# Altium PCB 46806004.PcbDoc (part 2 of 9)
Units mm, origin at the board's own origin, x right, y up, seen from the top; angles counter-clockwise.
Board outline 130 x 105 mm, 8 copper layers (Top Layer, P1-GND, L1-Signal, L2-Signal, L3-Signal, L4-Signal, P2-GND, Bottom Layer), stack 1.63 mm thick; 796 components, 496 nets, 2808 pads, 1195 vias.
Unrouted connection lines stored in the file: 1.
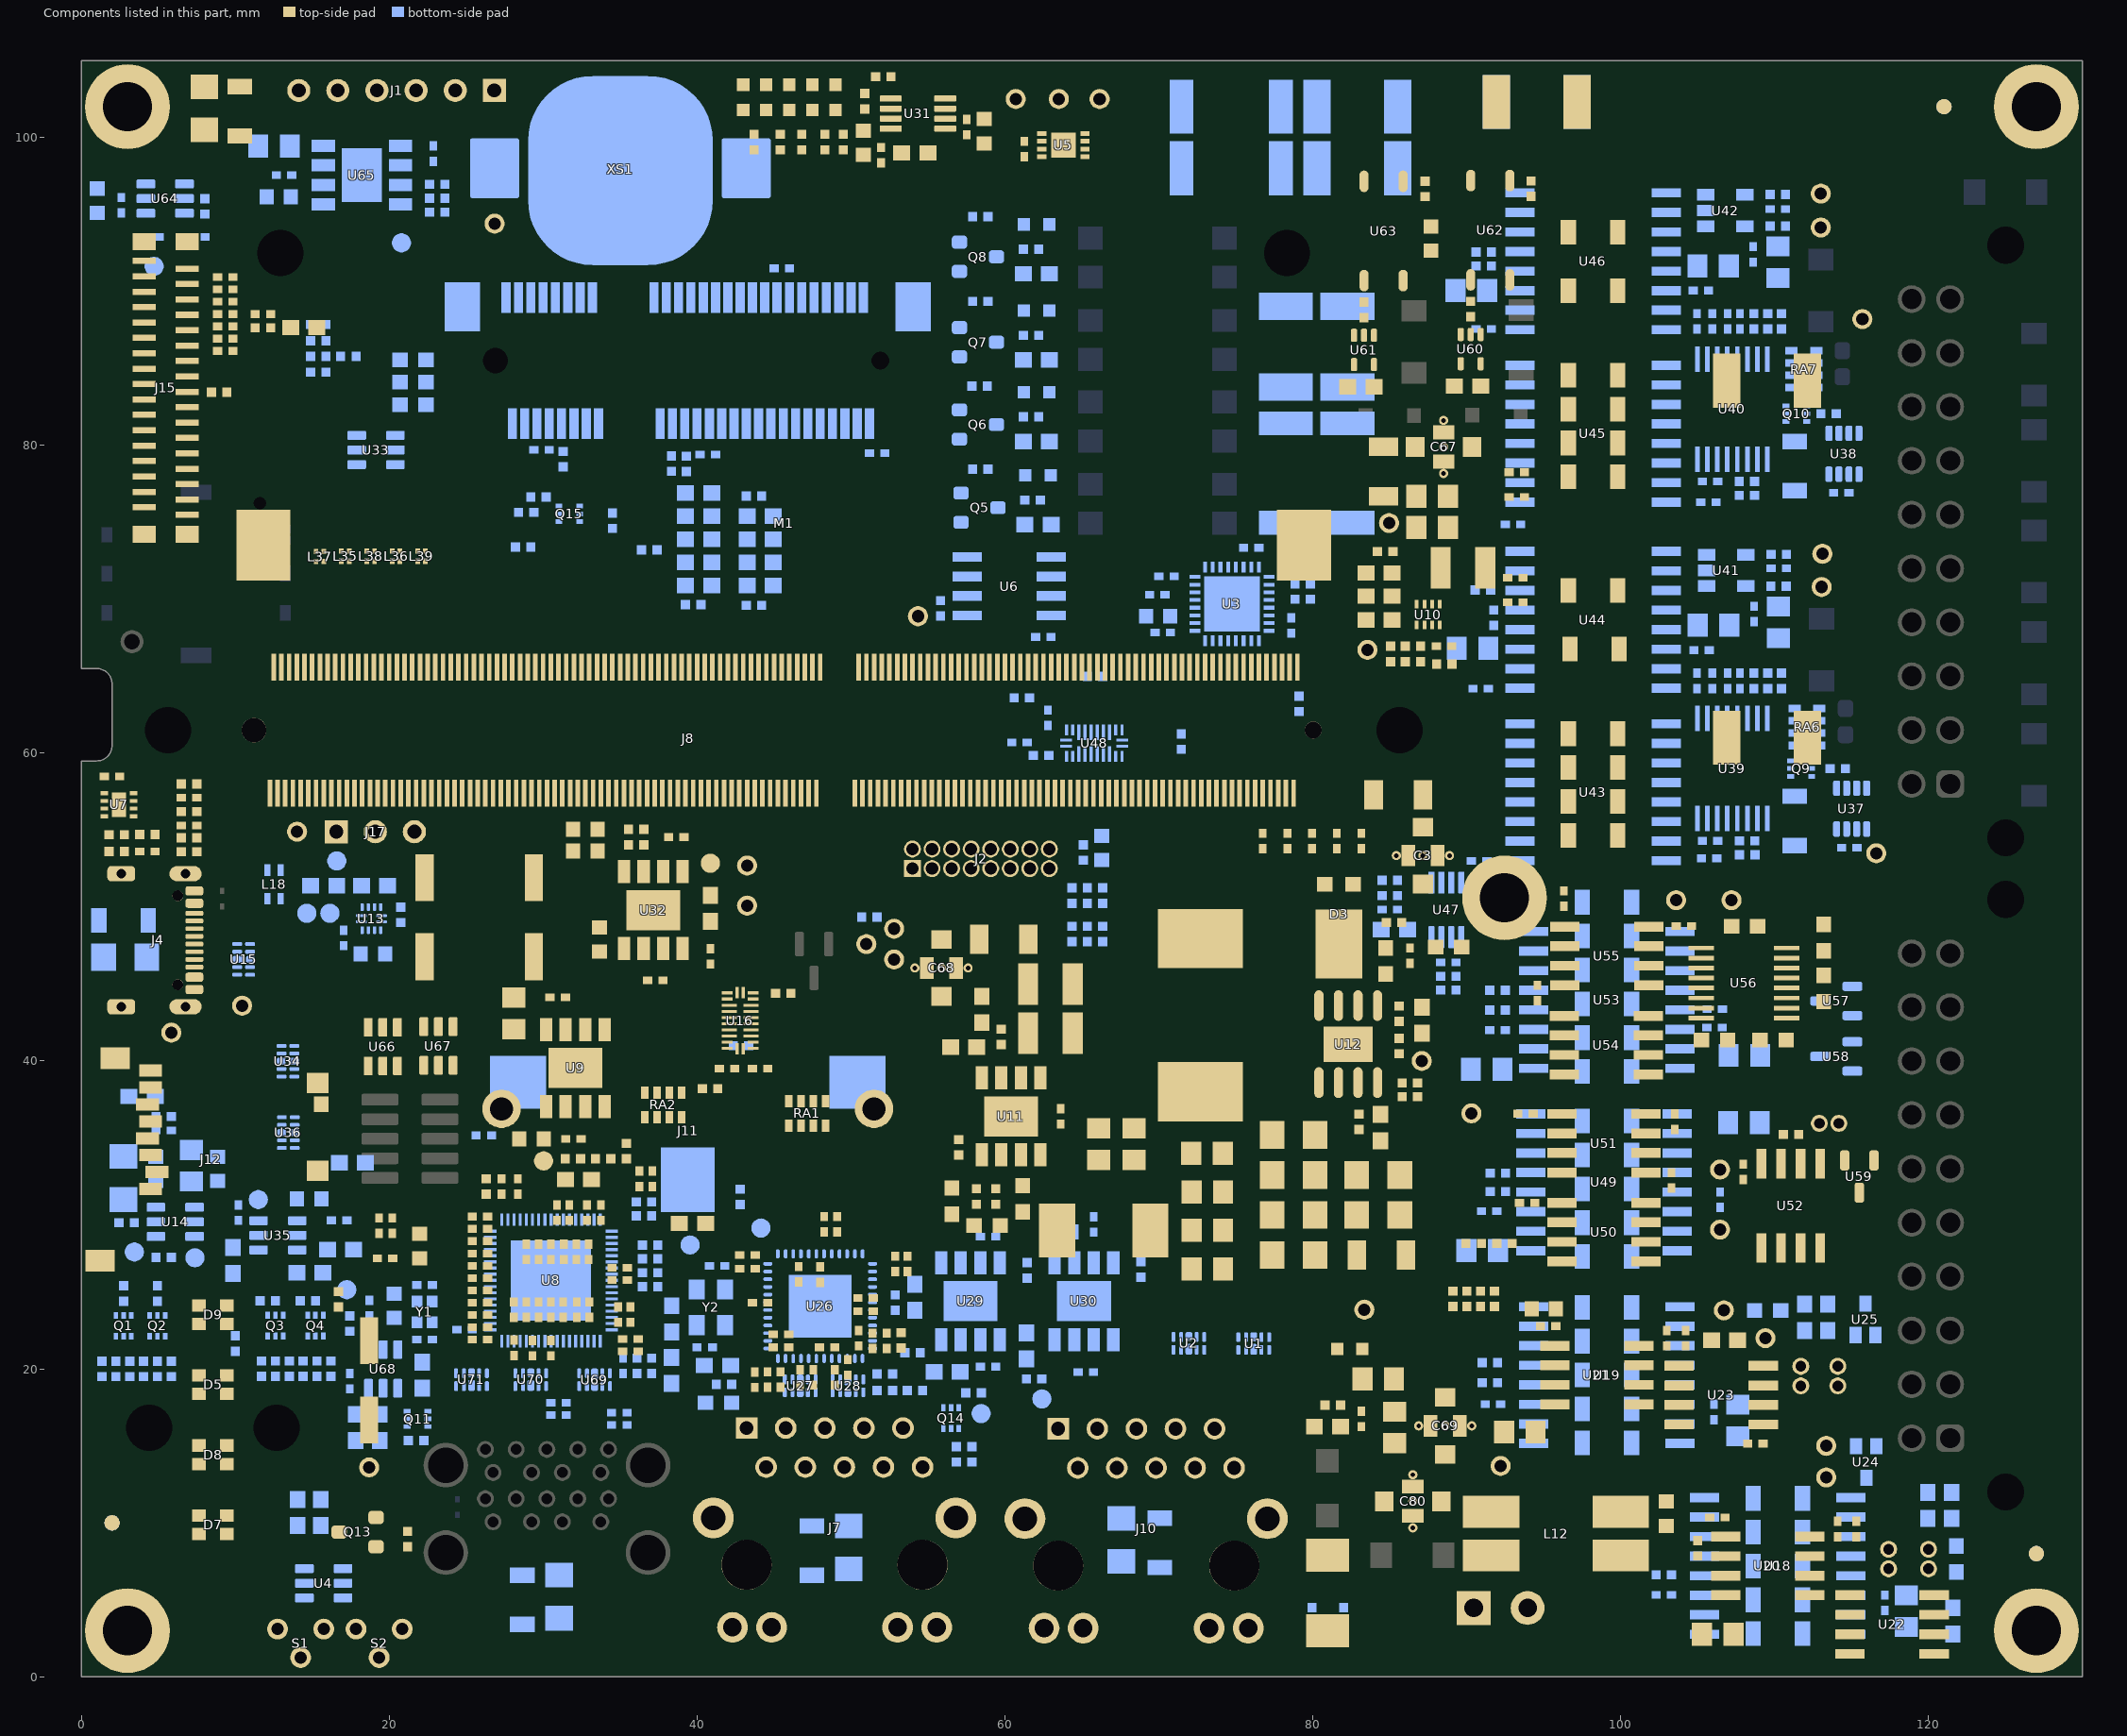
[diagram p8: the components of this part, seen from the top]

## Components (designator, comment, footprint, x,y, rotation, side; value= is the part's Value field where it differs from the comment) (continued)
Q7 "FDV301N" SOT23 58.247,86.699 r90 bottom
Q8 "FDV301N" SOT23 58.247,92.249 r90 bottom
Q9 "NTZD3154" SOT563 111.725,59 r0 bottom
Q10 "NTZD3154" SOT563 111.4,82.053 r0 bottom
Q11 "NTZD3154" SOT563 21.85,16.75 r0 bottom
Q13 "FDV301N" SOT23 17.95,9.4 r90 top
Q14 "NTZD3154" SOT563 56.5,16.8 r270 bottom
Q15 "NTZD3154" SOT563 31.7,75.55 r180 bottom
R1 "1552-Res-0402-120" R0402_RESC1005L 82,4 r90 bottom value=120
R2 "1552-Res-0402-120" R0402_RESC1005L 79.95,4 r90 bottom value=120
R3 "1860-Res-1206-1M-5%-0.25W" R/1206 70.05,8.7 r270 bottom value=1M/0.25W
R4 "1538-Res-0402-27k" R0402_RESC1005L 65.1,53.55 r90 bottom value=27K
R5 "0195-Res-0603-0.0ohm" R/0603 84.3,70.2 r180 top value=0.0
R6 "0000-Res-0603-DNP" R/0603 84.3,68.65 r180 top value=DNP
R7 "1650-Res-0402-1K" R0402_RESC1005L 2.3,54.7 r180 top value=1K
R8 "2199-Res-0603-60.4" R/0603 54.15,24.65 r90 bottom value=60.4
R9 "1572-Res-0402-10K" R0402_RESC1005L 79.338,70 r0 bottom value=10K
R10 "1572-Res-0402-10K" R0402_RESC1005L 79.338,71 r0 bottom value=10K
R11 "1536-Res-0402-1.87K" R0402_RESC1005L 55.817,69.411 r90 bottom value=1.87K
R12 "1572-Res-0402-10K" R0402_RESC1005L 36.95,28.05 r180 bottom value=10K
R13 "1572-Res-0402-10K" R0402_RESC1005L 36.95,27.15 r180 bottom value=10K
R14 "1977-Res-0402-100K" R0402_RESC1005L 36.1,20.2 r270 bottom value=100K
R15 "1572-Res-0402-10K" R0402_RESC1005L 37.05,20.2 r270 bottom value=10K
R16 "1572-Res-0402-10K" R0402_RESC1005L 21.75,15.35 r180 bottom value=10K
R17 "1572-Res-0402-10K" R0402_RESC1005L 36.95,25.35 r180 bottom value=10K
R18 "1572-Res-0402-10K" R0402_RESC1005L 36.95,26.25 r180 bottom value=10K
R19 "1973-Res-0603-100ohm" R/0603 38.35,23.25 r270 bottom value=100
R20 "1973-Res-0603-100ohm" R/0603 38.341,19.9 r270 bottom value=100
R21 "2075-Res-0402-6.04K" R0402_RESC1005L 26.3,31.85 r90 top value=6.04k
R22 "0000-Res-0603-DNP" R/0603 39.7,29.45 r0 top value=DNP
R23 "0195-Res-0603-0.0ohm" R/0603 32.3,32.3 r0 top value=0.0
R24 "1572-Res-0402-10K" R0402_RESC1005L 31.943,33.65 r180 top value=10K
R25 "1572-Res-0402-10K" R0402_RESC1005L 33.904,33.65 r180 top value=10K
R26 "1572-Res-0402-10K" R0402_RESC1005L 35.402,34.151 r270 top value=10K
R27 "1977-Res-0402-100K" R0402_RESC1005L 85.048,66.446 r90 top value=100K
R28 "1572-Res-0402-10K" R0402_RESC1005L 59.765,41.575 r90 top value=10K
R29 "0000-Res-0603-DNP" R/0603 58.5,43.35 r90 top value=DNP
R30 "1572-Res-0402-10K" R0402_RESC1005L 83,36.05 r270 top value=10K
R31 "0000-Res-0603-DNP" R/0603 84.4,35.678 r270 top value=DNP
R32 "1367-Res-0603-200K" R/0603 57.325,40.9 r0 top value=200K
R33 "1539-Res-0402-86.6k" R0402_RESC1005L 86.3,37.678 r180 top value=86.6K
R34 "1539-Res-0402-86.6k" R0402_RESC1005L 86.3,38.578 r180 top value=86.6K
R35 "1537-Res-0402-12K" R0402_RESC1005L 59.4,31.2 r90 top value=12K
R36 "1538-Res-0402-27k" R0402_RESC1005L 88.548,65.796 r0 top value=27K
R37 "1538-Res-0402-27k" R0402_RESC1005L 86.998,66.446 r270 top value=27K
R38 "1537-Res-0402-12K" R0402_RESC1005L 85.998,66.446 r90 top value=12K
R39 "1572-Res-0402-10K" R0402_RESC1005L 58.15,31.2 r270 top value=10K
R40 "1536-Res-0402-1.87K" R0402_RESC1005L 57,34.4 r270 top value=1.87K
R41 "1603-Res-0805-6.49K/0.25W" R/0805 85.3,16.2 r90 top value=6.49K/0.25W
R42 "1539-Res-0402-86.6k" R0402_RESC1005L 85.275,49 r180 top value=86.6K
R43 "1603-Res-0805-6.49K/0.25W" R/0805 84.25,19.35 r180 top value=6.49K/0.25W
R44 "1876-Res-0603-560K" R/0603 87.1,42.65 r270 top value=560K
R45 "1539-Res-0402-86.6k" R0402_RESC1005L 85.6,43.078 r90 top value=86.6K
R46 "1539-Res-0402-86.6k" R0402_RESC1005L 85.6,40.978 r90 top value=86.6K
R47 "2233-Res-0402-4.7K" R0402_RESC1005L 16.7,24.525 r90 top value=4.7K
R48 "1367-Res-0603-200K" R/0603 80.95,16.25 r180 top value=200K
R49 "2233-Res-0402-4.7K" R0402_RESC1005L 81.3,17.65 r0 top value=4.7K
R50 "2233-Res-0402-4.7K" R0402_RESC1005L 49.502,99.7 r270 top value=4.7K
R51 "1538-Res-0402-27k" R0402_RESC1005L 2.3,53.613 r180 top value=27K
R52 "1537-Res-0402-12K" R0402_RESC1005L 4.3,54.713 r180 top value=12K
R53 "1538-Res-0402-27k" R0402_RESC1005L 7,53.6 r180 top value=27K
R54 "1538-Res-0402-27k" R0402_RESC1005L 7,54.5 r0 top value=27K
R55 "1860-Res-1206-1M-5%-0.25W" R/1206 10.3,101.7 r270 top value=1M/0.25W
R56 "1537-Res-0402-12K" R0402_RESC1005L 7,58 r180 top value=12K
R57 "1538-Res-0402-27k" R0402_RESC1005L 7,56.2 r0 top value=27K
R58 "1538-Res-0402-27k" R0402_RESC1005L 51.2,49.35 r180 bottom value=27K
R59 "0000-Res-0603-DNP" R/0603 19.05,51.4 r0 bottom value=DNP
R60 "0000-Res-0603-DNP" R/0603 15.75,51.4 r0 bottom value=DNP
R61 "1538-Res-0402-27k" R0402_RESC1005L 5.35,27.25 r0 bottom value=27K
R62 "1538-Res-0402-27k" R0402_RESC1005L 2.95,29.5 r0 bottom value=27K
R63 "1538-Res-0402-27k" R0402_RESC1005L 5.35,36.4 r180 bottom value=27K
R64 "1809-Res-0402-887K" R0402_RESC1005L 20.75,49.5 r90 bottom value=887K
R65 "0728-Res-0603-274ohm" R/0603 3.95,37.7 r0 bottom value=274
R66 "1860-Res-1206-1M-5%-0.25W" R/1206 2.75,49.15 r180 bottom value=1M/0.25W
R67 "1572-Res-0402-10K" R0402_RESC1005L 2.75,24.9 r270 bottom value=10K
R68 "1536-Res-0402-1.87K" R0402_RESC1005L 1.35,20 r270 bottom value=1.87K
R69 "2233-Res-0402-4.7K" R0402_RESC1005L 3.15,20 r270 bottom value=4.7K
R70 "1572-Res-0402-10K" R0402_RESC1005L 2.25,20 r90 bottom value=10K
R71 "1572-Res-0402-10K" R0402_RESC1005L 4.95,24.9 r270 bottom value=10K
R72 "1536-Res-0402-1.87K" R0402_RESC1005L 4.05,20 r270 bottom value=1.87K
R73 "1536-Res-0402-1.87K" R0402_RESC1005L 5.85,20 r270 bottom value=1.87K
R74 "1572-Res-0402-10K" R0402_RESC1005L 4.95,20 r90 bottom value=10K
R75 "1572-Res-0402-10K" R0402_RESC1005L 12.114,24.415 r0 bottom value=10K
R76 "2233-Res-0402-4.7K" R0402_RESC1005L 11.714,20.015 r270 bottom value=4.7K
R77 "1536-Res-0402-1.87K" R0402_RESC1005L 13.514,20.015 r270 bottom value=1.87K
R78 "1572-Res-0402-10K" R0402_RESC1005L 12.614,20.015 r90 bottom value=10K
R79 "1572-Res-0402-10K" R0402_RESC1005L 14.714,24.415 r0 bottom value=10K
R80 "1536-Res-0402-1.87K" R0402_RESC1005L 14.414,20.015 r270 bottom value=1.87K
R81 "1572-Res-0402-10K" R0402_RESC1005L 15.314,20.015 r90 bottom value=10K
R82 "2233-Res-0402-4.7K" R0402_RESC1005L 10,21.65 r270 bottom value=4.7K
R83 "1536-Res-0402-1.87K" R0402_RESC1005L 16.214,20.015 r270 bottom value=1.87K
R84 "1539-Res-0402-86.6k" R0402_RESC1005L 65.85,64.993 r0 bottom value=86.6K
R85 "1536-Res-0402-1.87K" R0402_RESC1005L 39.75,69.65 r0 bottom value=1.87K
R86 "1977-Res-0402-100K" R0402_RESC1005L 105,8.35 r90 top value=100K
R87 "1977-Res-0402-100K" R0402_RESC1005L 91.5,20.4 r180 bottom value=100K
R88 "1650-Res-0402-1K" R0402_RESC1005L 102.8,6.62 r0 bottom value=1K
R89 "1650-Res-0402-1K" R0402_RESC1005L 91.5,19.1 r0 bottom value=1K
R90 "0038-Res-1206-0.0ohm" R/1206 99.1,24 r0 bottom value=0.0/1206
R91 "0038-Res-1206-0.0ohm" R/1206 110.2,11.59 r180 bottom value=0.0/1206
R92 "0195-Res-0603-0.0ohm" R/0603 121.567,3.626 r90 bottom value=0.0
R93 "0195-Res-0603-0.0ohm" R/0603 106.75,21.862 r180 top value=0.0
R94 "2199-Res-0603-60.4" R/0603 119.95,11.135 r90 bottom value=60.4
R95 "2199-Res-0603-60.4" R/0603 113.45,23.35 r270 bottom value=60.4
R96 "2199-Res-0603-60.4" R/0603 121.5,11.135 r90 bottom value=60.4
R97 "2199-Res-0603-60.4" R/0603 111.95,23.35 r270 bottom value=60.4
R98 "1536-Res-0402-1.87K" R0402_RESC1005L 61.797,76.449 r0 bottom value=1.87K
R99 "1536-Res-0402-1.87K" R0402_RESC1005L 61.697,81.849 r0 bottom value=1.87K
R100 "1536-Res-0402-1.87K" R0402_RESC1005L 61.697,87.149 r0 bottom value=1.87K
R101 "1536-Res-0402-1.87K" R0402_RESC1005L 61.697,92.749 r0 bottom value=1.87K
R102 "0864-Res-0603-680ohm" R/0603 62.147,74.849 r0 bottom value=680
R103 "0864-Res-0603-680ohm" R/0603 62.047,80.249 r0 bottom value=680
R104 "0864-Res-0603-680ohm" R/0603 62.047,85.549 r0 bottom value=680
R105 "0864-Res-0603-680ohm" R/0603 62.047,91.149 r0 bottom value=680
R106 "1538-Res-0402-27k" R0402_RESC1005L 58.397,78.449 r0 bottom value=27K
R107 "1538-Res-0402-27k" R0402_RESC1005L 58.347,83.849 r0 bottom value=27K
R108 "1538-Res-0402-27k" R0402_RESC1005L 58.397,89.349 r0 bottom value=27K
R109 "1538-Res-0402-27k" R0402_RESC1005L 58.397,94.849 r0 bottom value=27K
R110 "1424-Res-2512-10ohm-5%-2W" R/2512 78.25,78.2 r270 bottom value=10/2W/5%
R111 "1424-Res-2512-10ohm-5%-2W" R/2512 82.25,78.2 r270 bottom value=10/2W/5%
R112 "1424-Res-2512-10ohm-5%-2W" R/2512 74.7,102 r180 bottom value=10/2W/5%
R113 "1424-Res-2512-10ohm-5%-2W" R/2512 74.7,98 r180 bottom value=10/2W/5%
R114 "2313-Res-0402-2.49K" R0402_RESC1005L 65.35,48.25 r90 bottom value=2.49K
R115 "2077-Res-0402-5.76K" R0402_RESC1005L 65.35,50.75 r90 bottom value=5.76k
R116 "0000-Res-0402-DNP" R0402_RESC1005L 66.35,48.25 r90 bottom value=DNP
R117 "0000-Res-0402-DNP" R0402_RESC1005L 66.35,50.75 r270 bottom value=DNP
R118 "2313-Res-0402-2.49K" R0402_RESC1005L 64.35,48.25 r90 bottom value=2.49K
R119 "0195-Res-0603-0.0ohm" R/0603 41.325,20.225 r180 bottom value=0.0
R120 "2077-Res-0402-5.76K" R0402_RESC1005L 64.35,50.75 r90 bottom value=5.76k
R121 "1537-Res-0402-12K" R0402_RESC1005L 52.875,24.303 r90 bottom value=12K
R122 "2527-Res-0402-11K" R0402_RESC1005L 41.75,19 r180 bottom value=11K
R123 "1552-Res-0402-120" R0402_RESC1005L 57.85,14.45 r270 bottom value=120
R124 "1552-Res-0402-120" R0402_RESC1005L 56.85,14.45 r270 bottom value=120
R125 "1552-Res-0402-120" R0402_RESC1005L 61.45,26.4 r270 bottom value=120
R126 "1552-Res-0402-120" R0402_RESC1005L 68.825,26.45 r270 bottom value=120
R127 "1977-Res-0402-100K" R0402_RESC1005L 57.965,18.45 r0 bottom value=100K
R128 "0042-Res-0603-47K" R/0603 56.25,19.8 r180 bottom value=47K
R129 "1537-Res-0402-12K" R0402_RESC1005L 61.9,19.345 r0 bottom value=12K
R130 "0042-Res-0603-47K" R/0603 61.4,21.5 r90 bottom value=47K
R131 "1860-Res-1206-1M-5%-0.25W" R/1206 47.45,8.2 r270 bottom value=1M/0.25W
R132 "0000-Res-0603-DNP" R/0603 84.3,71.7 r0 top value=DNP
R133 "1538-Res-0402-27k" R0402_RESC1005L 84.7,73.1 r0 top value=27K
R134 "1367-Res-0603-200K" R/0603 54.15,99 r0 top value=200K
R135 "1536-Res-0402-1.87K" R0402_RESC1005L 43.7,99.7 r270 top value=1.87K
R136 "2233-Res-0402-4.7K" R0402_RESC1005L 50.9,102.35 r90 top value=4.7K
R137 "2233-Res-0402-4.7K" R0402_RESC1005L 52.1,103.95 r180 top value=4.7K
R138 "2199-Res-0603-60.4" R/0603 40.865,49.92 r90 top value=60.4
R139 "1537-Res-0402-12K" R0402_RESC1005L 31.3,79.1 r270 bottom value=12K
R140 "1536-Res-0402-1.87K" R0402_RESC1005L 43.7,76.7 r0 bottom value=1.87K
R141 "1538-Res-0402-27k" R0402_RESC1005L 38.34,78.816 r90 bottom value=27K
R142 "0195-Res-0603-0.0ohm" R/0603 44.1,73.9 r0 bottom value=0.0
R143 "0195-Res-0603-0.0ohm" R/0603 44.1,72.4 r0 bottom value=0.0
R144 "0195-Res-0603-0.0ohm" R/0603 44.1,70.9 r0 bottom value=0.0
R145 "0195-Res-0603-0.0ohm" R/0603 44.1,75.4 r0 bottom value=0.0
R146 "1538-Res-0402-27k" R0402_RESC1005L 39.3,78.8 r90 bottom value=27K
R147 "1536-Res-0402-1.87K" R0402_RESC1005L 43.7,69.6 r0 bottom value=1.87K
R148 "2199-Res-0603-60.4" R/0603 40.1,76.9 r0 bottom value=60.4
R149 "1572-Res-0402-10K" R0402_RESC1005L 36.55,54.55 r90 top value=10K
R150 "1537-Res-0402-12K" R0402_RESC1005L 35.55,54.55 r270 top value=12K
R151 "1536-Res-0402-1.87K" R0402_RESC1005L 45.4,99.7 r270 top value=1.87K
R152 "1536-Res-0402-1.87K" R0402_RESC1005L 46.8,99.7 r270 top value=1.87K
R153 "1536-Res-0402-1.87K" R0402_RESC1005L 48.3,99.7 r270 top value=1.87K
R154 "0000-Res-0603-DNP" R/0603 16.85,27.75 r0 bottom value=DNP
R155 "0728-Res-0603-274ohm" R/0603 14.85,26.25 r0 bottom value=274
R156 "0042-Res-0603-47K" R/0603 9.85,27.05 r270 bottom value=47K
R157 "0000-Res-0603-DNP" R/0603 17.616,33.4 r0 bottom value=DNP
R158 "1192-Res-1206-100ohm-0.01%-0.5W" R/1206 111.3,55.6 r90 bottom value=100/0.01%/0.5W
R159 "1192-Res-1206-100ohm-0.01%-0.5W" R/1206 111.3,78.653 r90 bottom value=100/0.01%/0.5W
R160 "1536-Res-0402-1.87K" R0402_RESC1005L 108.21,54.3 r180 bottom value=1.87K
R161 "1536-Res-0402-1.87K" R0402_RESC1005L 108.217,53.4 r180 bottom value=1.87K
R162 "1536-Res-0402-1.87K" R0402_RESC1005L 108.2,77.65 r180 bottom value=1.87K
R163 "1536-Res-0402-1.87K" R0402_RESC1005L 108.2,76.75 r180 bottom value=1.87K
R164 "1018-Res-0402-6.49K" R0402_RESC1005L 110.2,94.25 r0 bottom value=6.49K
R165 "1018-Res-0402-6.49K" R0402_RESC1005L 110.247,70.852 r0 bottom value=6.49K
R166 "1572-Res-0402-10K" R0402_RESC1005L 110.2,96.3 r180 bottom value=10K
R167 "1572-Res-0402-10K" R0402_RESC1005L 110.26,72.915 r180 bottom value=10K
R168 "2233-Res-0402-4.7K" R0402_RESC1005L 110.45,64.7 r90 bottom value=4.7K
R169 "2233-Res-0402-4.7K" R0402_RESC1005L 110.45,88.05 r90 bottom value=4.7K
R170 "2233-Res-0402-4.7K" R0402_RESC1005L 109.55,64.7 r90 bottom value=4.7K
R171 "2233-Res-0402-4.7K" R0402_RESC1005L 109.55,88.05 r90 bottom value=4.7K
R172 "2233-Res-0402-4.7K" R0402_RESC1005L 108.65,64.7 r90 bottom value=4.7K
R173 "2233-Res-0402-4.7K" R0402_RESC1005L 108.65,88.05 r90 bottom value=4.7K
R174 "1539-Res-0402-86.6k" R0402_RESC1005L 113.5,82.053 r180 bottom value=86.6K
R175 "1539-Res-0402-86.6k" R0402_RESC1005L 114.1,59 r180 bottom value=86.6K
R176 "1650-Res-0402-1K" R0402_RESC1005L 91.05,70.6 r0 bottom value=1K
R177 "1977-Res-0402-100K" R0402_RESC1005L 91.75,68.8 r270 bottom value=100K
R178 "1650-Res-0402-1K" R0402_RESC1005L 91.1,91.653 r0 bottom value=1K
R179 "1977-Res-0402-100K" R0402_RESC1005L 91.1,92.553 r180 bottom value=100K
R180 "2233-Res-0402-4.7K" R0402_RESC1005L 85,51.745 r180 bottom value=4.7K
R181 "2233-Res-0402-4.7K" R0402_RESC1005L 85,50.745 r180 bottom value=4.7K
R182 "1367-Res-0603-200K" R/0603 85.3,48.545 r0 bottom value=200K
R183 "1536-Res-0402-1.87K" R0402_RESC1005L 88.8,45.5 r0 bottom value=1.87K
R184 "1536-Res-0402-1.87K" R0402_RESC1005L 88.8,44.62 r0 bottom value=1.87K
R185 "1537-Res-0402-12K" R0402_RESC1005L 90.45,28.15 r0 top value=12K
R186 "1018-Res-0402-6.49K" R0402_RESC1005L 92.45,28.15 r180 top value=6.49K
R187 "1977-Res-0402-100K" R0402_RESC1005L 92.022,32.723 r180 bottom value=100K
R188 "1650-Res-0402-1K" R0402_RESC1005L 92.022,31.523 r0 bottom value=1K
R189 "0038-Res-1206-0.0ohm" R/1206 99.1,29.5 r180 bottom value=0.0/1206
R190 "1552-Res-0402-120" R0402_RESC1005L 111.063,35.228 r0 top value=120
R191 "1977-Res-0402-100K" R0402_RESC1005L 92,44.607 r180 bottom value=100K
R192 "1650-Res-0402-1K" R0402_RESC1005L 92,43.307 r0 bottom value=1K
R193 "1536-Res-0402-1.87K" R0402_RESC1005L 90.255,88.848 r270 top value=1.87K
R194 "1536-Res-0402-1.87K" R0402_RESC1005L 83.325,88.8 r270 top value=1.87K
R195 "0728-Res-0603-274ohm" R/0603 90.055,83.848 r0 top value=274
R196 "0728-Res-0603-274ohm" R/0603 83.125,83.8 r0 top value=274
R197 "1572-Res-0402-10K" R0402_RESC1005L 94.175,96.673 r90 top value=10K
R198 "1572-Res-0402-10K" R0402_RESC1005L 87.295,96.653 r90 top value=10K
R199 "0000-Res-0402-DNP" R0402_RESC1005L 8.95,83.45 r180 top value=DNP
R200 "1572-Res-0402-10K" R0402_RESC1005L 15.4,84.75 r180 bottom value=10K
R201 "0000-Res-0402-DNP" R0402_RESC1005L 15.4,85.775 r180 bottom value=DNP
R202 "1572-Res-0402-10K" R0402_RESC1005L 17.35,85.775 r180 bottom value=10K
R203 "2233-Res-0402-4.7K" R0402_RESC1005L 23.125,96.95 r0 bottom value=4.7K
R204 "1536-Res-0402-1.87K" R0402_RESC1005L 23.125,96.05 r180 bottom value=1.87K
R205 "1536-Res-0402-1.87K" R0402_RESC1005L 23.125,95.15 r0 bottom value=1.87K
R206 "1572-Res-0402-10K" R0402_RESC1005L 8.031,95.528 r90 bottom value=10K
R207 "1536-Res-0402-1.87K" R0402_RESC1005L 15.4,86.8 r180 bottom value=1.87K
R208 "1536-Res-0402-1.87K" R0402_RESC1005L 15.4,87.85 r180 bottom value=1.87K
R209 "0195-Res-0603-0.0ohm" R/0603 14.45,87.65 r180 top value=0.0
R210 "1572-Res-0402-10K" R0402_RESC1005L 11.8,87.628 r180 top value=10K
R211 "1572-Res-0402-10K" R0402_RESC1005L 36.55,29.95 r0 bottom value=10K
R212 "1572-Res-0402-10K" R0402_RESC1005L 36.55,30.85 r180 bottom value=10K
R213 "0687-Res-0603-6.8K" R/0603 19.39,16.2 r90 bottom value=6.8K
R214 "1860-Res-1206-1M-5%-0.25W" R/1206 28.65,5 r270 bottom value=1M/0.25W
R215 "1572-Res-0402-10K" R0402_RESC1005L 42.85,41 r0 bottom value=10K
R216 "0687-Res-0603-6.8K" R/0603 17.831,16.2 r270 bottom value=6.8K
R217 "0195-Res-0603-0.0ohm" R/0603 22.15,19.6 r90 bottom value=0.0
R218 "0195-Res-0603-0.0ohm" R/0603 15.55,10.675 r270 bottom value=0.0
R219 "0195-Res-0603-0.0ohm" R/0603 14.05,10.675 r270 bottom value=0.0
R220 "1536-Res-0402-1.87K" R0402_RESC1005L 42.8,31.175 r90 bottom value=1.87K
R221 "1572-Res-0402-10K" R0402_RESC1005L 53.25,21.85 r270 top value=10K
R222 "1572-Res-0402-10K" R0402_RESC1005L 45.6,44.4 r180 top value=10K
R223 "1538-Res-0402-27k" R0402_RESC1005L 17.45,22.95 r90 bottom value=27K
R224 "1536-Res-0402-1.87K" R0402_RESC1005L 36.9,73.2 r180 bottom value=1.87K
R225 "1572-Res-0402-10K" R0402_RESC1005L 90,24.55 r270 top value=10K
R226 "1572-Res-0402-10K" R0402_RESC1005L 90.9,24.55 r270 top value=10K
R227 "1572-Res-0402-10K" R0402_RESC1005L 89.1,24.55 r270 top value=10K
R228 "1572-Res-0402-10K" R0402_RESC1005L 91.8,24.55 r270 top value=10K
R229 "0195-Res-0603-0.0ohm" R/0603 40.1,75.4 r180 bottom value=0.0
R230 "0195-Res-0603-0.0ohm" R/0603 40.1,72.4 r180 bottom value=0.0
R231 "0195-Res-0603-0.0ohm" R/0603 40.1,70.9 r180 bottom value=0.0
R232 "0195-Res-0603-0.0ohm" R/0603 40.1,73.9 r180 bottom value=0.0
R233 "0038-Res-1206-0.0ohm" R/1206 110.2,2.8 r180 bottom value=0.0/1206
R234 "0038-Res-1206-0.0ohm" R/1206 110.2,7.2 r0 bottom value=0.0/1206
R235 "0038-Res-1206-0.0ohm" R/1206 110.2,5 r0 bottom value=0.0/1206
R236 "0038-Res-1206-0.0ohm" R/1206 110.2,9.4 r0 bottom value=0.0/1206
R237 "0038-Res-1206-0.0ohm" R/1206 99.1,19.6 r0 bottom value=0.0/1206
R238 "0038-Res-1206-0.0ohm" R/1206 99.1,21.8 r0 bottom value=0.0/1206
R239 "0038-Res-1206-0.0ohm" R/1206 99.1,17.4 r0 bottom value=0.0/1206
R240 "0038-Res-1206-0.0ohm" R/1206 99.1,15.2 r0 bottom value=0.0/1206
R241 "0038-Res-1206-0.0ohm" R/1206 99.1,27.3 r180 bottom value=0.0/1206
R242 "0038-Res-1206-0.0ohm" R/1206 99.1,33.9 r180 bottom value=0.0/1206
R243 "0038-Res-1206-0.0ohm" R/1206 99.1,31.7 r180 bottom value=0.0/1206
R244 "0038-Res-1206-0.0ohm" R/1206 99.1,36.118 r180 bottom value=0.0/1206
R245 "0038-Res-1206-0.0ohm" R/1206 99.1,48.118 r180 bottom value=0.0/1206
R246 "0038-Res-1206-0.0ohm" R/1206 99.1,50.318 r180 bottom value=0.0/1206
R247 "0038-Res-1206-0.0ohm" R/1206 99.1,45.918 r180 bottom value=0.0/1206
R248 "0038-Res-1206-0.0ohm" R/1206 99.1,43.718 r180 bottom value=0.0/1206
R249 "0038-Res-1206-0.0ohm" R/1206 99.1,41.518 r180 bottom value=0.0/1206
R250 "0038-Res-1206-0.0ohm" R/1206 99.1,39.318 r180 bottom value=0.0/1206
R251 "0038-Res-1206-0.0ohm" R/1206 98.2,59.063 r0 top value=0.0/1206
R252 "0038-Res-1206-0.0ohm" R/1206 98.2,54.663 r0 top value=0.0/1206
R253 "0038-Res-1206-0.0ohm" R/1206 98.2,61.263 r0 top value=0.0/1206
R254 "0038-Res-1206-0.0ohm" R/1206 98.2,56.863 r0 top value=0.0/1206
R255 "0038-Res-1206-0.0ohm" R/1206 98.3,66.763 r0 top value=0.0/1206
R256 "0038-Res-1206-0.0ohm" R/1206 98.2,70.563 r0 top value=0.0/1206
R257 "0038-Res-1206-0.0ohm" R/1206 98.2,82.353 r0 top value=0.0/1206
R258 "0038-Res-1206-0.0ohm" R/1206 98.2,77.953 r0 top value=0.0/1206
R259 "0038-Res-1206-0.0ohm" R/1206 98.2,84.553 r0 top value=0.0/1206
R260 "0038-Res-1206-0.0ohm" R/1206 98.2,80.153 r0 top value=0.0/1206
R261 "0038-Res-1206-0.0ohm" R/1206 98.2,90.053 r0 top value=0.0/1206
R262 "0038-Res-1206-0.0ohm" R/1206 98.2,93.853 r0 top value=0.0/1206
R263 "1572-Res-0402-10K" R0402_RESC1005L 21.2,8.95 r270 top value=10K
R264 "2233-Res-0402-4.7K" R0402_RESC1005L 29.7,76.65 r0 bottom value=4.7K
R265 "0000-Res-0402-DNP" R0402_RESC1005L 54,21.05 r180 bottom value=DNP
R266 "0000-Res-0402-DNP" R0402_RESC1005L 54.15,18.6 r0 bottom value=DNP
R267 "0000-Res-0402-DNP" R0402_RESC1005L 52.2,19.672 r0 bottom value=DNP
R268 "0000-Res-0402-DNP" R0402_RESC1005L 52.2,18.6 r180 bottom value=DNP
R269 "2233-Res-0402-4.7K" R0402_RESC1005L 34.5,75.1 r270 bottom value=4.7K
R270 "2233-Res-0402-4.7K" R0402_RESC1005L 28.7,73.4 r0 bottom value=4.7K
R271 "2233-Res-0402-4.7K" R0402_RESC1005L 28.9,75.65 r0 bottom value=4.7K
R272 "1572-Res-0402-10K" R0402_RESC1005L 40.85,38.2 r0 top value=10K
R273 "1572-Res-0402-10K" R0402_RESC1005L 62.35,59.85 r0 bottom value=10K
R274 "1572-Res-0402-10K" R0402_RESC1005L 61.1,63.6 r180 bottom value=10K
R275 "1572-Res-0402-10K" R0402_RESC1005L 71.45,60.75 r270 bottom value=10K
R276 "1572-Res-0402-10K" R0402_RESC1005L 79.1,63.2 r270 bottom value=10K
RA1 "1407-ResArr-1206-10K" RESNET-1206-4 47.15,36.6 r0 top value="4 x 10K"
RA2 "1407-ResArr-1206-10K" RESNET-1206-4 37.8,37.15 r0 top value="4 x 10K"
RA6 "2066A-ResArr-1206-10kohm-30kohm" RESNET-1206-4 112.1,61.7 r90 bottom
RA7 "2066A-ResArr-1206-10kohm-30kohm" RESNET-1206-4 111.9,84.95 r90 bottom
S1 "PB" "BUTTON TC-1109DE-C-A" 14.25,2.175 r0 top locked
S2 "PB" "BUTTON TC-1109DE-C-A" 19.35,2.175 r0 top locked
U1 "DT1240-04LP-7" 10-UFDFN 76.163,21.645 r90 bottom
U2 "DT1240-04LP-7" 10-UFDFN 71.95,21.658 r90 bottom
U3 "SLM9670AQ20FW1311XTMA1" QFN50P500X500X90-33N-V 74.75,69.7 r0 bottom
U4 "TPD4E001" SOT23-6 15.75,6.075 r90 bottom
U5 "M24C02-FMC6TG" M24C02FMC6TG 63.8,99.5 r90 top
U6 "MB85RS256TYPNF-G-BCERE1" SOIC-8 60.286,70.846 r0 bottom
U7 "TMP1075DSGR" WSON-8(2.1x2.1)_PAD 2.45,56.65 r180 top
U8 "CYUSB3304-68LTXI" QFN68_LT68B_CYP 30.511,25.747 r270 bottom locked
U9 "AP2132BMP-2.5TRG1" "SOP-9 TP_ALT" 32.1,39.55 r270 top
U10 "TPS62823DLCR" DLC0008A 87.498,68.996 r90 top
U11 "AP64500SP-13" "SOP-9 TP_ALT" 60.4,36.4 r270 top
U12 "LM5013DDAR" "SOP-9 TP" 82.3,41.1 r90 top
U13 "TUSB320LIRWBR" QFN40P160X160X40-12N 18.85,49.25 r0 bottom
U14 "BD2222G" sot23-6 6.105,29.55 r270 bottom
U15 "DT1240-04LP-7" 10-UFDFN 10.545,46.6 r0 bottom
U16 "SN74AXC8T245RJWR" UQFN-24 42.8,42.625 r180 top
U18 "UCC12040DVER" SOIC-16 110.2,7.2 r90 bottom
U19 "UCC12040DVER" SOIC-16 99.1,19.6 r90 bottom
U20 "ISO6721RBDR" SOIC-8 109.55,7.2 r0 top
U21 "ISO6721RBDR" SOIC-8 98.45,19.6 r0 top
U22 "TCAN1044VDRQ1" SOIC-8 117.63,3.395 r0 top
U23 "TCAN1044VDRQ1" SOIC-8 106.531,18.295 r0 top
U24 "ESDCAN06-2BWY" SOT-323 115.95,13.95 r0 bottom
U25 "ESDCAN06-2BWY" SOT-323 115.9,23.225 r180 bottom
U26 "DP83867ERGZR" RGZ0048B 48,24.075 r90 bottom
U27 "DT1240-04LP-7" 10-UFDFN 46.7,18.9 r270 bottom
U28 "DT1240-04LP-7" 10-UFDFN 49.8,18.9 r270 bottom
U29 "AP2132BMP-2.5TRG1" "SOP-9 TP_ALT" 57.765,24.4 r270 bottom
U30 "AP2132BMP-2.5TRG1" "SOP-9 TP_ALT" 65.135,24.4 r270 bottom
U31 "PCA9306DCT" TSSO3x5-G8/X.35 54.35,101.55 r90 top
U32 "AP2132BMP-2.5" "SOP-9 TP_ALT" 37.165,49.8 r90 top
U33 "TPD4E001" SOT23-6 19.15,79.7 r270 bottom
U34 "DT1240-04LP-7" 10-UFDFN 13.425,39.987 r180 bottom
U35 "AP22653AW6-7" sot23-6 12.771,28.681 r270 bottom
U36 "DT1240-04LP-7" 10-UFDFN 13.45,35.35 r180 bottom
U37 "TPS26614DDFR" TSOT-23-8_TEX 115,56.4 r270 bottom
U38 "TPS26614DDFR" TSOT-23-8_TEX 114.5,79.453 r270 bottom
U39 "ADS1119" TSSOP16 107.25,59 r90 bottom
U40 "ADS1119" TSSOP16 107.25,82.35 r90 bottom
U41 "AP2202K-ADJ" SOT23-5 106.86,71.868 r90 bottom
U42 "AP2202K-ADJ" SOT23-5 106.8,95.253 r90 bottom
U43 "ISO1644DWR" SOIC-16 98.2,57.463 r90 bottom
U44 "UCC12040DVER" SOIC-16 98.2,68.663 r90 bottom
U45 "ISO1644DWR" SOIC-16 98.2,80.753 r90 bottom
U46 "UCC12040DVER" SOIC-16 98.2,91.953 r90 bottom
U47 "PCA9306DCT" TSSO3x5-G8/X.35 88.675,49.82 r180 bottom
U48 "SN74AXC8T245RJWR" UQFN-24 65.8,60.65 r270 bottom
U49 "UCC12040DVER" SOIC-16 98.922,32.123 r90 bottom locked
U50 "ISO6721RBDR" SOIC-8 98.922,28.887 r0 top
U51 "ISO6721RBDR" SOIC-8 98.922,34.663 r0 top
U52 "SN65176BDR" SOIC-8 111.05,30.6 r90 top
U53 "UCC12040DVER" SOIC-16 99.1,43.968 r90 bottom locked
U54 "ISO6721RBDR" SOIC-8 99.077,41.029 r0 top
U55 "ISO6721RBDR" SOIC-8 99.1,46.829 r0 top
U56 "ST3232BTR" PW016 108,45.068 r90 top
U57 "PESD15VL2BT,215" SOT23_N 114,43.9 r180 bottom
U58 "PESD15VL2BT,215" SOT23_N 114,40.3 r180 bottom
U59 "PESD15VL2BT,215" SOT23_N 115.5,32.5 r270 top
U60 "PSSI2021" SOT353-5N 90.255,86.248 r270 top
U61 "PSSI2021" SOT353-5N 83.325,86.2 r270 top
U62 "TLP185GR" SOP254P700X210-4N 91.525,93.973 r90 top
U63 "TLP185GR" SOP254P700X210-4N 84.595,93.925 r90 top
U64 "AP22653AW6-7" sot23-6 5.45,96.028 r90 bottom
U65 "AP2132BMP-2.5TRG1" "SOP-9 TP_ALT" 18.225,97.55 r0 bottom
U66 "TPD4E001" SOT23-6 19.587,40.93 r0 top
U67 "TPD4E001" SOT23-6 23.2,40.98 r0 top
U68 "AP22653AW6-7" sot23-6 19.611,20 r0 bottom
U69 "DT1240-04LP-7" 10-UFDFN 33.35,19.3 r270 bottom
U70 "DT1240-04LP-7" 10-UFDFN 29.2,19.3 r90 bottom
U71 "DT1240-04LP-7" 10-UFDFN 25.35,19.3 r90 bottom
X1 "000-TestPoint" TestPoint_1 83.35,23.85 r0 top
X2 "000-TestPoint" TestPoint_1 66.15,102.5 r90 top
X3 "000-TestPoint" TestPoint_1 26.85,94.4 r0 top
X4 "000-TestPoint" TestPoint_1 52.8,46.6 r0 top
X5 "000-TestPoint" TestPoint_1 51,47.6 r0 top
X6 "000-TestPoint" TestPoint_1 84.95,74.95 r0 top
X7 "000-TestPoint" TestPoint_1 52.8,48.6 r0 top
X8 "000-TestPoint2" TestPoint_3 80.55,72.65 r270 bottom
X9 "000-TestPoint" TestPoint_1 63.5,102.5 r180 top
X10 "000-TestPoint" TestPoint_1 60.7,102.5 r180 top
X11 "000-TestPoint" TestPoint_1 54.35,68.9 r90 bottom
X13 "000-TestPoint2" TestPoint_3 39.548,28.05 r270 bottom
X14 "000-TestPoint2" TestPoint_3 30.033,33.51 r0 top
X15 "000-TestPoint" TestPoint_1 83.55,66.715 r0 top
X16 "000-TestPoint" TestPoint_1 92.2,13.7 r0 top
X17 "000-TestPoint" TestPoint_1 90.3,36.6 r0 top
X18 "000-TestPoint" TestPoint_1 87.075,40.007 r0 top
X19 "000-TestPoint" TestPoint_1 10.45,43.6 r270 top
X20 "000-TestPoint2" TestPoint_3 7.386,27.22 r90 bottom
X21 "000-TestPoint2" TestPoint_3 16.6,53 r270 bottom
X22 "000-TestPoint2" TestPoint_3 3.45,27.6 r0 bottom
X23 "000-TestPoint2" TestPoint_3 14.65,49.6 r270 bottom
X24 "000-TestPoint2" TestPoint_3 16.15,49.6 r270 bottom
X25 "000-TestPoint" TestPoint_1 5.85,41.85 r270 top
X30 "000-TestPoint" TestPoint_1 113.35,15 r0 top
X31 "000-TestPoint" TestPoint_1 109.4,22 r0 top
X32 "000-TestPoint" TestPoint_1 113.35,12.95 r0 top
X33 "000-TestPoint" TestPoint_1 106.7,23.8 r0 top
X51 "000-TestPoint2" TestPoint_3 44.15,29.15 r270 bottom
X52 "000-TestPoint2" TestPoint_3 58.45,17.1 r180 bottom
X53 "000-TestPoint2" TestPoint_3 62.4,18.05 r180 bottom
X55 "000-TestPoint2" TestPoint_3 40.865,52.85 r90 top
X56 "000-TestPoint2" TestPoint_3 17.25,25.15 r0 bottom
X57 "000-TestPoint2" TestPoint_3 11.5,31 r180 bottom
X58 "000-TestPoint" TestPoint_1 113,94.15 r0 top
X59 "000-TestPoint" TestPoint_1 113.05,70.8 r0 top
X60 "000-TestPoint" TestPoint_1 113,96.353 r0 top
X61 "000-TestPoint" TestPoint_1 113.1,72.95 r0 top
X62 "000-TestPoint" TestPoint_1 116.6,53.5 r0 top
X63 "000-TestPoint" TestPoint_1 115.7,88.2 r0 top
X64 "000-TestPoint" TestPoint_1 43.25,52.7 r0 top
X65 "000-TestPoint" TestPoint_1 43.25,50.1 r0 top
X69 "000-TestPoint" TestPoint_1 106.448,32.95 r180 top
X70 "000-TestPoint" TestPoint_1 106.45,29.05 r180 top
X77 "000-TestPoint" TestPoint_1 103.6,50.45 r0 top
X78 "000-TestPoint" TestPoint_1 107.2,50.45 r0 top
X79 "000-TestPoint" TestPoint_1 14.02,54.9 r0 top
X80 "000-TestPoint2" TestPoint_3 20.8,93.15 r0 bottom
X81 "000-TestPoint2" TestPoint_3 4.729,91.625 r0 bottom
X83 "000-TestPoint" TestPoint_1 18.7,13.6 r0 top
XS1 "1216/12202/1225" T_KEYSTONE_3000 35.02,98 r180 bottom locked
Y1 "2097-Xtal 26MHz 2.0x1.6mm" OSC_4-SMD_(2.0x1.6) 22.3,23.7 r180 bottom value="26 MHz"
Y2 "0987-Xtal 25MHz 3.2x2.5mm" XTAL_CX3225 40.9,24 r90 bottom value="25 MHz"

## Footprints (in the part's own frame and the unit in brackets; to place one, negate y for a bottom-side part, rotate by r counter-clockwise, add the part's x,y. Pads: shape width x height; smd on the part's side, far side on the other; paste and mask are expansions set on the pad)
4-PLCC_LED_2121_BROADCOM [mm] "4-SMD, J-Lead 2.10mm L x 2.10mm W"
  rect 0.9x0.8 smd: 1(0.9,-0.6) 2(0.9,0.6) 3(-0.9,0.6) 4(-0.9,-0.6)
  silkscreen extent -0.25,-1.5 1,1.02, body extent -1.05,-1.05 1.05,1.05, height 1
10-UFDFN [mm] "TVS Diode Surface Mount U-DFN2510-10 (2.5x1.0mm)"
  rrect50% 0.625x0.25 smd mask+0.074: 1(-0.417,1) 2(-0.417,0.5) 4(-0.417,-0.5) 5(-0.417,-1) 6(0.417,-1) 7(0.417,-0.5) 9(0.417,0.5) 10(0.417,1)
  rrect50% 0.7x0.45 smd mask+0.09: 3(-0.375,0)
  rrect50% 0.575x0.45 smd mask+0.09: 8(0.442,0)
  silkscreen extent -1.05,-1.3 0.56,1.31, body extent -0.5,-1.25 0.5,1.25, height 0.5
17758622_FULL_SIZE [mm] "Full size (30x50.95 mm), ONE latch.  Card thickness: 1.0mm."
  rect 0.6x2 smd: 1(-11.8,-28.6) 2(-11.4,-20.4) 3(-11,-28.6) 4(-10.6,-20.4) 5(-10.2,-28.6) 6(-9.8,-20.4) 7(-9.4,-28.6) 8(-9,-20.4) 9(-8.6,-28.6) 10(-8.2,-20.4) 11(-7.8,-28.6) 12(-7.4,-20.4) 13(-7,-28.6) 14(-6.6,-20.4) 15(-6.2,-28.6) 16(-5.8,-20.4) 17(-2.2,-28.6) 18(-1.8,-20.4) 19(-1.4,-28.6) 20(-1,-20.4) 21(-0.6,-28.6) 22(-0.2,-20.4) 23(0.2,-28.6) 24(0.6,-20.4) 25(1,-28.6) 26(1.4,-20.4) 27(1.8,-28.6) 28(2.2,-20.4) 29(2.6,-28.6) 30(3,-20.4) 31(3.4,-28.6) 32(3.8,-20.4) 33(4.2,-28.6) 34(4.6,-20.4) 35(5,-28.6) 36(5.4,-20.4) 37(5.8,-28.6) 38(6.2,-20.4) 39(6.6,-28.6) 40(7,-20.4) 41(7.4,-28.6) 42(7.8,-20.4) 43(8.2,-28.6) 44(8.6,-20.4) 45(9,-28.6) 46(9.4,-20.4) 47(9.8,-28.6) 48(10.2,-20.4) 49(10.6,-28.6) 50(11,-20.4) 51(11.4,-28.6) 52(11.8,-20.4)
  round 0.825 hole 1.65 unplated: MH1(-12.5,-24.5)
  round 2.5 hole 1.5: MH1(-12.1,24.1) MH2(12.1,24.1)
  rect 3.65x3.45 smd: MH1(-11.013,22.375) MH2(11.028,22.375)
  round 0.575 hole 1.15 unplated: MH2(12.5,-24.5)
  rect 3.5x4.2 smd: MH3(0,28.7)
  rect 2.3x3.2 smd: MP1(-14.65,-28) MP2(14.65,-28)
  Top Layer keep-out lines w0.05: -15,30.8 -4.05,30.8 -4.05,28.65 -1.95,28.65 -1.95,26.35 -15,26.35 -15,30.8 ; 1.95,28.65 4.05,28.65 4.05,30.8 15,30.8 15,26.35 1.95,26.35 1.95,28.65
  silkscreen extent -14.95,-29 14.95,20.88, body extent -15,-29.04 15,30.27, height 6.15
AMPHENOL_F314-1A7H1-11034 [mm]
  rect 0.4x1.5 smd: 1(-8.25,-1.4) 2(-7.75,1.4) 3(-7.25,-1.4) 4(-6.75,1.4) 5(-6.25,-1.4) 6(-5.75,1.4) 7(-5.25,-1.4) 8(-4.75,1.4) 9(-4.25,-1.4) 10(-3.75,1.4) 11(-3.25,-1.4) 12(-2.75,1.4) 13(-2.25,-1.4) 14(-1.75,1.4) 15(-1.25,-1.4) 16(-0.75,1.4) 17(-0.25,-1.4) 18(0.25,1.4) 19(0.75,-1.4) 20(1.25,1.4) 21(1.75,-1.4) 22(2.25,1.4) 23(2.75,-1.4) 24(3.25,1.4) 25(3.75,-1.4) 26(4.25,1.4) 27(4.75,-1.4) 28(5.25,1.4) 29(5.75,-1.4) 30(6.25,1.4) 31(6.75,-1.4) 32(7.25,1.4) 33(7.75,-1.4) 34(8.25,1.4)
  rect 1.1x1.5 smd: SH1(-9.5,-1.4) SH2(-9.5,1.4) SH3(9.5,1.4) SH4(9.5,-1.4)
  silkscreen extent -12.05,-1.17 12.05,3.7, body extent -12.07,-1.78 12.04,1.78, height 4.25
"BUTTON TC-1109DE-C-A" [mm]
  round 1.35 hole 0.8: 1(-1.5,0.925) 2(1.5,0.925) 3(0,-0.925)
  silkscreen extent -2.25,-0.92 2.25,1.88, body extent -2.25,-1.93 2.25,1.87, height 4.5
C0402_CAPC1005L [mm] "Chip Capacitor, Body 1.0x0.5mm, IPC High Density"
  rect 0.6x0.5 smd: 1(-0.5,0) 2(0.5,0)
  silkscreen extent 0,-0.27 0,0.28, body extent -0.52,-0.27 0.52,0.28, height 0.54
C/0603 [mm] "CAP CER 0603 (1608 Metric)"
  rect 1x0.95 smd: 1(-0.85,0) 2(0.85,0)
  silkscreen extent -1.58,-0.7 1.3,0.7, body extent -0.8,-0.4 0.8,0.4, height 0.8
C/0805 [mm]
  rect 1.3x1.5 smd: 1(-1.025,0) 2(1.025,0)
  silkscreen extent -1.9,-1 1.5,1, body extent -1,-0.64 1,0.64, height 1.3
C/1206 [mm] "CAP 1206 (3216 Metric)"
  rect 1.6x1.8 smd: 1(-1.4,0) 2(1.4,0)
  silkscreen extent -2.45,-1.15 2.1,1.15, body extent -1.85,-0.97 1.85,0.97, height 1.84
C/1206_3P [mm]
  rect 1.2x1.3 smd: 1(-1.85,0) 3(1.85,0)
  rect 1.4x0.9 smd: 2(0,0.95) 2(0,-0.95)
  round 0.6 hole 0.3 mask+0.102: 2(0,1.725) 2(0,0) 2(0,-1.725)
  Top Layer region: -0.381,2.032 -0.7,1.713 -0.7,-1.713 -0.381,-2.032 0.381,-2.032 0.7,-1.713 0.7,1.713 0.381,2.032
  body extent -1.6,-0.8 1.6,0.8, height 1.29
CAN-SMD-D630 [mm] "CAN-SMD 6.60mm x 6.60mm x 6.10mm"
  rect 3.042x1.187 smd paste+0 mask+0: 1(-2.573,0) 2(2.573,0)
  Top Layer keep-out region: -0.9,-0.644 -0.9,0.644 0.9,0.644 0.9,-0.644
  silkscreen extent -3.43,-3.43 3.43,3.43, body extent -3.65,-3.3 3.65,3.3, height 7.7
CAPC3225N [mm] "Chip Capacitor, Body 3.2x2.5mm (1210), IPC Medium Density"
  rect 1.3x2.7 smd: 1(-1.45,0) 2(1.45,0)
  silkscreen extent -0.4,-1.25 0.4,1.25, body extent -1.6,-1.25 1.6,1.25, height 2.5
CNC_CONN16_3210-16-001-12-00 [mm] "CONN HEADER TH VERT 16POS 1.27MM"
  rect 1.1x1.1 hole 0.8 mask+0.1: 1(-4.445,-0.635)
  round 1.1 hole 0.8 mask+0.1: 2(-4.445,0.635) 3(-3.175,-0.635) 4(-3.175,0.635) 5(-1.905,-0.635) 6(-1.905,0.635) 7(-0.635,-0.635) 8(-0.635,0.635) 9(0.635,-0.635) 10(0.635,0.635) 11(1.905,-0.635) 12(1.905,0.635) 13(3.175,-0.635) 14(3.175,0.635) 15(4.445,-0.635) 16(4.445,0.635)
  silkscreen extent -12.32,-3.05 12.32,3.05, body extent -12.25,-2.75 12.26,2.75, height 11.1
COIL0302 [mm] "0302 (0806 Metric), 4 Lead"
  rect 0.3x0.35 smd: 1(-0.25,-0.325) 2(0.25,-0.325) 3(0.25,0.325) 4(-0.25,0.325)
  silkscreen extent -0.61,-0.81 0.61,0.34, body extent -0.43,-0.33 0.43,0.33, height 0.5
COMMON_CHOKE_BOURNS_SRF2012-900YA [mm] "2.0x1.2x1.2mm"
  rect 0.75x0.4 smd: 1(-0.925,0.425) 2(0.925,0.425) 3(0.925,-0.425) 4(-0.925,-0.425)
  silkscreen extent -1.65,-0.58 0.36,0.58, body extent -1,-0.6 1,0.6, height 1.2
COMMON_CHOKE_Laird_CM3421Y600R-10 [mm]
  rect 3.66x2.08 smd: 1(-4.21,1.42) 2(-4.21,-1.42) 3(4.21,-1.42) 4(4.21,1.42)
  silkscreen extent -4.34,-2.8 4.34,2.8, body extent -4.77,-2.8 4.77,2.8, height 3.8
CON-TE-2309409-2_TORADEX_VERDIN_MTG_rev2 [mm]
  round 0 hole 3 unplated: 0(-40,13.45) 0(40,13.45) 1(-32.7,-17.55) 1(32.7,-17.554)
  rect 0.3x1.75 smd mask+0.05: 1(33.375,17.55) 2(33.125,9.35) 3(32.875,17.55) 4(32.625,9.35) 5(32.375,17.55) 6(32.125,9.35) 7(31.875,17.55) 8(31.625,9.35) 9(31.375,17.55) 10(31.125,9.35) 11(30.875,17.55) 12(30.625,9.35) 13(30.375,17.55) 14(30.125,9.35) 15(29.875,17.55) 16(29.625,9.35) 17(29.375,17.55) 18(29.125,9.35) 19(28.875,17.55) 20(28.625,9.35) 21(28.375,17.55) 22(28.125,9.35) 23(27.875,17.55) 24(27.625,9.35) 25(27.375,17.55) 26(27.125,9.35) 27(26.875,17.55) 28(26.625,9.35) 29(26.375,17.55) 30(26.125,9.35) 31(25.875,17.55) 32(25.625,9.35) 33(25.375,17.55) 34(25.125,9.35) 35(24.875,17.55) 36(24.625,9.35) 37(24.375,17.55) 38(24.125,9.35) 39(23.875,17.55) 40(23.625,9.35) 41(23.375,17.55) 42(23.125,9.35) 43(22.875,17.55) 44(22.625,9.35) 45(22.375,17.55) 46(22.125,9.35) 47(21.875,17.55) 48(21.625,9.35) 49(21.375,17.55) 50(21.125,9.35) 51(20.875,17.55) 52(20.625,9.35) 53(20.375,17.55) 54(20.125,9.35) 55(19.875,17.55) 56(19.625,9.35) 57(19.375,17.55) 58(19.125,9.35) 59(18.875,17.55) 60(18.625,9.35) 61(18.375,17.55) 62(18.125,9.35) 63(17.875,17.55) 64(17.625,9.35) 65(17.375,17.55) 66(17.125,9.35) 67(16.875,17.55) 68(16.625,9.35) 69(16.375,17.55) 70(16.125,9.35) 71(15.875,17.55) 72(15.625,9.35) 73(15.375,17.55) 74(15.125,9.35) 75(14.875,17.55) 76(14.625,9.35) 77(14.375,17.55) 78(14.125,9.35) 79(13.875,17.55) 80(13.625,9.35) 81(13.375,17.55) 82(13.125,9.35) 83(12.875,17.55) 84(12.625,9.35) 85(12.375,17.55) 86(12.125,9.35) 87(11.875,17.55) 88(11.625,9.35) 89(11.375,17.55) 90(11.125,9.35) 91(10.875,17.55) 92(10.625,9.35) 93(10.375,17.55) 94(10.125,9.35) 95(9.875,17.55) 96(9.625,9.35) 97(9.375,17.55) 98(9.125,9.35) 99(8.875,17.55) 100(8.625,9.35) 101(8.375,17.55) 102(8.125,9.35) 103(7.875,17.55) 104(7.625,9.35) 105(7.375,17.55) 106(7.125,9.35) 107(6.875,17.55) 108(6.625,9.35) 109(6.375,17.55) 110(6.125,9.35) 111(5.875,17.55) 112(5.625,9.35) 113(5.375,17.55) 114(5.125,9.35) 115(4.875,17.55) 116(4.625,9.35) 117(4.375,17.55) 118(4.125,9.35) 119(3.875,17.55) 120(3.625,9.35) 121(3.375,17.55) 122(3.125,9.35) 123(2.875,17.55) 124(2.625,9.35) 125(2.375,17.55) 126(2.125,9.35) 127(1.875,17.55) 128(1.625,9.35) 129(1.375,17.55) 130(1.125,9.35) 131(0.875,17.55) 132(0.625,9.35) 133(0.375,17.55) 134(0.125,9.35) 135(-0.125,17.55) 136(-0.375,9.35) 137(-0.625,17.55) 138(-0.875,9.35) 139(-1.125,17.55) 140(-1.375,9.35) 141(-1.625,17.55) 142(-1.875,9.35) 143(-2.125,17.55) 144(-2.375,9.35) 145(-4.625,17.55) 146(-4.875,9.35) 147(-5.125,17.55) 148(-5.375,9.35) 149(-5.625,17.55) 150(-5.875,9.35) 151(-6.125,17.55) 152(-6.375,9.35) 153(-6.625,17.55) 154(-6.875,9.35) 155(-7.125,17.55) 156(-7.375,9.35) 157(-7.625,17.55) 158(-7.875,9.35) 159(-8.125,17.55) 160(-8.375,9.35) 161(-8.625,17.55) 162(-8.875,9.35) 163(-9.125,17.55) 164(-9.375,9.35) 165(-9.625,17.55) 166(-9.875,9.35) 167(-10.125,17.55) 168(-10.375,9.35) 169(-10.625,17.55) 170(-10.875,9.35) 171(-11.125,17.55) 172(-11.375,9.35) 173(-11.625,17.55) 174(-11.875,9.35) 175(-12.125,17.55) 176(-12.375,9.35) 177(-12.625,17.55) 178(-12.875,9.35) 179(-13.125,17.55) 180(-13.375,9.35) 181(-13.625,17.55) 182(-13.875,9.35) 183(-14.125,17.55) 184(-14.375,9.35) 185(-14.625,17.55) 186(-14.875,9.35) 187(-15.125,17.55) 188(-15.375,9.35) 189(-15.625,17.55) 190(-15.875,9.35) 191(-16.125,17.55) 192(-16.375,9.35) 193(-16.625,17.55) 194(-16.875,9.35) 195(-17.125,17.55) 196(-17.375,9.35) 197(-17.625,17.55) 198(-17.875,9.35) 199(-18.125,17.55) 200(-18.375,9.35) 201(-18.625,17.55) 202(-18.875,9.35) 203(-19.125,17.55) 204(-19.375,9.35) 205(-19.625,17.55) 206(-19.875,9.35) 207(-20.125,17.55) 208(-20.375,9.35) 209(-20.625,17.55) 210(-20.875,9.35) 211(-21.125,17.55) 212(-21.375,9.35) 213(-21.625,17.55) 214(-21.875,9.35) 215(-22.125,17.55) 216(-22.375,9.35) 217(-22.625,17.55) 218(-22.875,9.35) 219(-23.125,17.55) 220(-23.375,9.35) 221(-23.625,17.55) 222(-23.875,9.35) 223(-24.125,17.55) 224(-24.375,9.35) 225(-24.625,17.55) 226(-24.875,9.35) 227(-25.125,17.55) 228(-25.375,9.35) 229(-25.625,17.55) 230(-25.875,9.35) 231(-26.125,17.55) 232(-26.375,9.35) 233(-26.625,17.55) 234(-26.875,9.35) 235(-27.125,17.55) 236(-27.375,9.35) 237(-27.625,17.55) 238(-27.875,9.35) 239(-28.125,17.55) 240(-28.375,9.35) 241(-28.625,17.55) 242(-28.875,9.35) 243(-29.125,17.55) 244(-29.375,9.35) 245(-29.625,17.55) 246(-29.875,9.35) 247(-30.125,17.55) 248(-30.375,9.35) 249(-30.625,17.55) 250(-30.875,9.35) 251(-31.125,17.55) 252(-31.375,9.35) 253(-31.625,17.55) 254(-31.875,9.35) 255(-32.125,17.55) 256(-32.375,9.35) 257(-32.625,17.55) 258(-32.875,9.35) 259(-33.125,17.55) 260(-33.375,9.35)
  round 1.1 hole 1.1 unplated: ""(-34.4,13.45)
  rect 3.5x4.6 smd: ""(-33.8,1.45) ""(33.8,1.45)
  round 1.6 hole 1.6 unplated: ""(34.4,13.45)
  Top Layer circle w1: c32.7,-17.554 r2.15
  Top Layer circle w1: c-32.7,-17.55 r2.15
  Top Layer circle w0.9: c-40,13.45 r2.2
  Top Layer circle w0.9: c40,13.45 r2.2
  Top Layer keep-out circle w0.05: c32.7,-17.554 r2.85
  Top Layer keep-out circle w0.05: c-32.7,-17.55 r2.85
  silkscreen extent -36.7,-7.65 36.7,19.48, body extent -36.5,-21.55 36.5,18.48, height 6.8
CONN_WVN-RC_SUL [mm] "CONN HEADER VERT 2POS 1.27MM"
  round 1.1 hole 0.7 paste-2539.97 mask+0: 1(-0.635,0) 2(0.635,0)
  silkscreen extent -1.65,-1.19 1.4,1.19, body extent -1.27,-1.2 1.27,1.2, height 4.85
DLC0008A [mm]
  rect 0.55x0.25 smd paste+0 mask+0.051: 1(-0.675,0.75) 2(-0.675,0.25) 3(-0.675,-0.25) 4(-0.675,-0.75) 5(0.675,-0.75) 6(0.675,-0.25) 7(0.675,0.25) 8(0.675,0.75)
  silkscreen extent -1.25,-1.15 0.75,1.15, body extent -0.76,-0.99 0.74,1.01, height 0.92
EATON_DR127 [mil] "15 µH Shielded Drum Core, Wirewound Inductor 5.03 A 24.7mOhm Nonstandard"
  rect 152x217 smd paste+0 mask+0: 1(-196,0) 2(196,0)
  Top Layer keep-out region: -108.27,-244 -108.27,244 108.27,244 108.27,-244
  silkscreen extent -251,-251 251,251, body extent -246,-246 246,246, height 315
FID_40X120_RND [mm]
  round 1 smd paste-1 mask+1: 1(0,0)
  Top Layer keep-out circle w0.05: c0,0 r1.3
FUSC6125X279N [mm] "Fuse Board Mount (Cartridge Style Excluded) Surface Mount 2-SMD, Square End Block (6.10mm x 2.54mm x 2.79mm)"
  rect 2.15x2.8 smd: 1(-2.455,0) 2(2.455,0)
  silkscreen extent -1,-1.27 1,1.27, body extent -3.05,-1.27 3.05,1.27, height 2.79
GCT_USB4105GFA120 [mm] "USB-C (USB TYPE-C) USB 2.0 Receptacle Connector 24 (16+8 Dummy) Position Surface Mount, Right Angle; Through Hole"
  rrect50% 0.6x1.15 smd mask+0.074: A1/B12(-3.2,2.378) A4/B9(-2.4,2.378) B1/A12(3.2,2.378) B4/A9(2.4,2.378)
  rrect50% 0.3x1.15 smd mask+0.074: A5(-1.25,2.378) A6(-0.25,2.378) A7(0.25,2.378) A8(1.25,2.378) B5(1.75,2.378) B6(0.75,2.378) B7(-0.75,2.378) B8(-1.75,2.378)
  oval 1x2.1 hole 0.6 slot 1.7 at 90 deg: SH1(-4.32,1.803) SH2(4.32,1.803)
  rrect50% 1x1.8 hole 0.6 slot 1.4 at 90 deg: SH3(-4.32,-2.377) SH4(4.32,-2.377)
  round 0.7 hole 0.7 unplated mask+0.1: ""(-2.89,1.303) ""(2.89,1.303)
  silkscreen extent -4.47,-4.65 4.47,3.68, body extent -4.47,-4.98 4.47,2.72, height 3.26
HDR1X3 [mm] "Connector; Header; 3 Position"
  rect 1.5x1.5 hole 0.9: 1(-2.54,0)
  round 1.5 hole 0.9: 2(0,0) 3(2.54,0)
  silkscreen extent -3.75,-1.75 3.75,1.27
HDR1X6 [mm] "Connector; Header; 4 Position"
  rect 1.5x1.5 hole 0.9: 1(-6.35,0)
  round 1.5 hole 0.9: 2(-3.81,0) 3(-1.27,0) 4(1.27,0) 5(3.81,0) 6(6.35,0)
  silkscreen extent -7.62,-1.27 7.62,1.85
INDC1608x095 [mm] "FERRITE BEAD 0603 (1608 Metric)"
  rect 0.92x0.98 smd: 1(-0.79,0) 2(0.79,0)
  Top Layer keep-out region: -0.15,-0.45 -0.15,0.45 0.15,0.45 0.15,-0.45
  silkscreen extent -0.15,-0.53 0.15,0.53, body extent -0.8,-0.4 0.8,0.4, height 0.8
INDC3225N [mm] "Chip Inductor, Body 3.2x2.5mm, IPC Medium Density / 3D - INDC3225x135N"
  rect 1.3x2.7 smd: 1(-1.45,0) 2(1.45,0)
  silkscreen extent -0.4,-1.25 0.4,1.25, body extent -1.6,-1.25 1.6,1.25, height 1.35
INDP1206 [mm] "Chip Inductor, Body 3.2x1.6mm, IPC Medium Density"
  rect 1.2x1.9 smd: 1(-1.6,0) 2(1.6,0)
  silkscreen extent -0.6,-0.85 0.6,0.85, body extent -1.6,-0.8 1.6,0.8, height 1.3
INDP_7.3X6.6N [mm]
  rect 2.35x3.5 smd: 1(-3.025,0) 2(3.025,0)
  silkscreen extent -3.65,-3.3 3.65,3.3, body extent -3.65,-3.3 3.65,3.3, height 3
LABEL_0.25x0.9IN [mm]
  silkscreen extent 0,0 23.37,6.86
LABEL_10x10mm_ALT [mm]
  silkscreen extent 0,0 10,10
LED-SMT-0603_APT1608CGCK [mm] "LED SMT Green, 2-Leads, Body 1,00x0,80mm, IPC Medium Density"
  rect 0.8x0.8 smd: 1(-0.825,0) 2(0.825,0)
  silkscreen extent -1.5,-0.69 1.68,0.69, body extent -0.8,-0.4 0.8,0.4, height 0.6
LPF-S014331S [mm] "LIGHT PIPE 3.2X3.18MM 4POS RECT"
  round 0 hole 3 unplated: 0(0,4.14) 0(0,-4.14)
  silkscreen extent -9.06,-5.97 8.55,5.97, body extent -9.06,-5.97 19.69,5.97, height 21.63
M24C02FMC6TG [mm]
  rect 0.3x0.6 smd: 1(-0.75,-1.4) 2(-0.25,-1.4) 3(0.25,-1.4) 4(0.75,-1.4) 5(0.75,1.4) 6(0.25,1.4) 7(-0.25,1.4) 8(-0.75,1.4)
  rect 1.6x1.6 smd: 9(0,0)
  silkscreen extent -0.8,-2.1 -0.7,-2, body extent -0.99,-1.5 1.01,1.5, height 0.62
MEM2051-00-195-00-A_REVC [mm] "Micro SD Memory Card Connector, 1.88mm Profile SMT,Push Push, with normally closed switch"
  rect 0.8x1.5 smd: 1(1.915,-3.898) 2(0.815,-3.498) 3(-0.285,-3.898) 4(-1.385,-4.098) 5(-2.485,-3.898) 6(-3.585,-4.098) 7(-4.685,-3.898) 8(-5.785,-3.898)
  rect 1x0.95 smd: 9(-3.585,7.187)
  rect 1.3x1.4 smd: 10(-4.975,6.963) 13(0.725,6.963)
  rect 1.4x1.9 smd: 11(-6.575,-6.188) 12(6.575,-7.187)
  Top Layer keep-out region: -2.835,1.125 -2.835,5.255 -4.335,5.255 -4.335,1.125
  Top Layer keep-out region: -6.275,1.132 2.425,1.132 2.425,3.432 -6.275,3.432
  silkscreen extent -7.02,-8.04 6.98,7.36, body extent -7.05,-7.6 7.05,7.75, height 1.95
MINI_PCIE_52PIN_CARD_LATCH_ALT [mm] "Creator MM"
  rect 3.65x3.45 smd: 1(-11.013,-6.325) 2(11.028,-6.325)
  rect 3.5x4.2 smd: 3(0,0)
  rrect70% 0x0 hole 1.5: 7(-12.1,-4.597) 8(12.1,-4.597)
  body extent -14.1,-7.87 14.1,1.48, height 4.79
MTG_HOLE_0.125#1 [mm] "Mounting hole 0,125\""
  round 5.5 hole 3.2 paste-2539.97: 0(0,0)
MTG_HOLE_0.125#2 [mm] "Mounting hole 0,125\""
  round 5.5 hole 3.2 paste-2539.97: 0(-0.1,0)
MTG_HOLE_0.125#3 [mm] "Mounting hole 0,125\" (3.2 mm)"
  round 5.5 / inner round 0 / far side round 0 hole 3.2 paste-2539.97: 0(0,0)
"MTG_POST WURTH 774070243" [mm] "SMT Steel Spacer with internal Thread M2, height 7mm"
  round 0 hole 3 unplated: 0(0,0)
  Top Layer circle w0.9: c0,0 r2.2
  body extent -2.17,-2.17 2.18,2.17, height 7
OSC_4-SMD_(2.0x1.6) [mm] "4-SMD, No Lead (2.00mm x 1.60mm)"
  rect 0.7x0.75 smd: 1(-0.5,0.675) 2(-0.5,-0.675) 3(0.5,-0.675) 4(0.5,0.675)
  silkscreen extent -1.3,-1.3 1.1,1.3, body extent -0.8,-1 0.8,1, height 0.7
Phoenix_1727566 [mm]
  rect 2.2x2.2 hole 1.2: 1(-1.75,0)
  round 2.2 hole 1.2: 2(1.75,0)
  silkscreen extent -8.68,-4.07 8.64,1.24, body extent -8.67,-7.97 8.63,1.23, height 7.25
POWERDI-5_DIO [mil] "Diodes PowerDI5"
  rect 37x39 smd paste+0 mask+0: 1(-111.5,36.22) 2(-111.5,-36.22)
  rect 177x120 smd paste+0 mask+0: 3(41.5,0)
  silkscreen extent -113,-85 113,85, body extent -130,-79 130,79, height 45
PTC_1812 [mm] "Polymeric PTC Resettable Fuse Surface Mount 1812 (4532 Metric), Concave"
  rect 1.78x3.5 smd paste+0 mask+0: 1(-2.616,0) 2(2.616,0)
  Top Layer keep-out region: -1.575,-1.702 -1.575,1.702 1.575,1.702 1.575,-1.702
  silkscreen extent -1.4,-1.83 1.4,1.83, body extent -2.27,-1.62 2.28,1.62, height 0.7
PULSE_JXD0-0025NL [mm]
  round 3.25 hole 3.25 unplated: 0(-5.715,-2.415) 0(5.715,-2.415)
  rect 1.4x1.4 hole 0.9: 1(-5.715,6.475)
  round 1.4 hole 0.9: 2(-4.445,3.935) 3(-3.175,6.475) 4(-1.905,3.935) 5(-0.635,6.475) 6(0.635,3.935) 7(1.905,6.475) 8(3.175,3.935) 9(4.445,6.475) 10(5.715,3.935)
  round 2 hole 1.2: 11(-6.63,-6.475) 12(-4.09,-6.475) 13(4.09,-6.475) 14(6.63,-6.475)
  round 2.65 hole 1.6: S(-7.875,0.635) S(7.875,0.635)
  silkscreen extent -7.92,-9.22 7.89,8.18, body extent -9.95,-13.17 10.05,8.18, height 15.5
